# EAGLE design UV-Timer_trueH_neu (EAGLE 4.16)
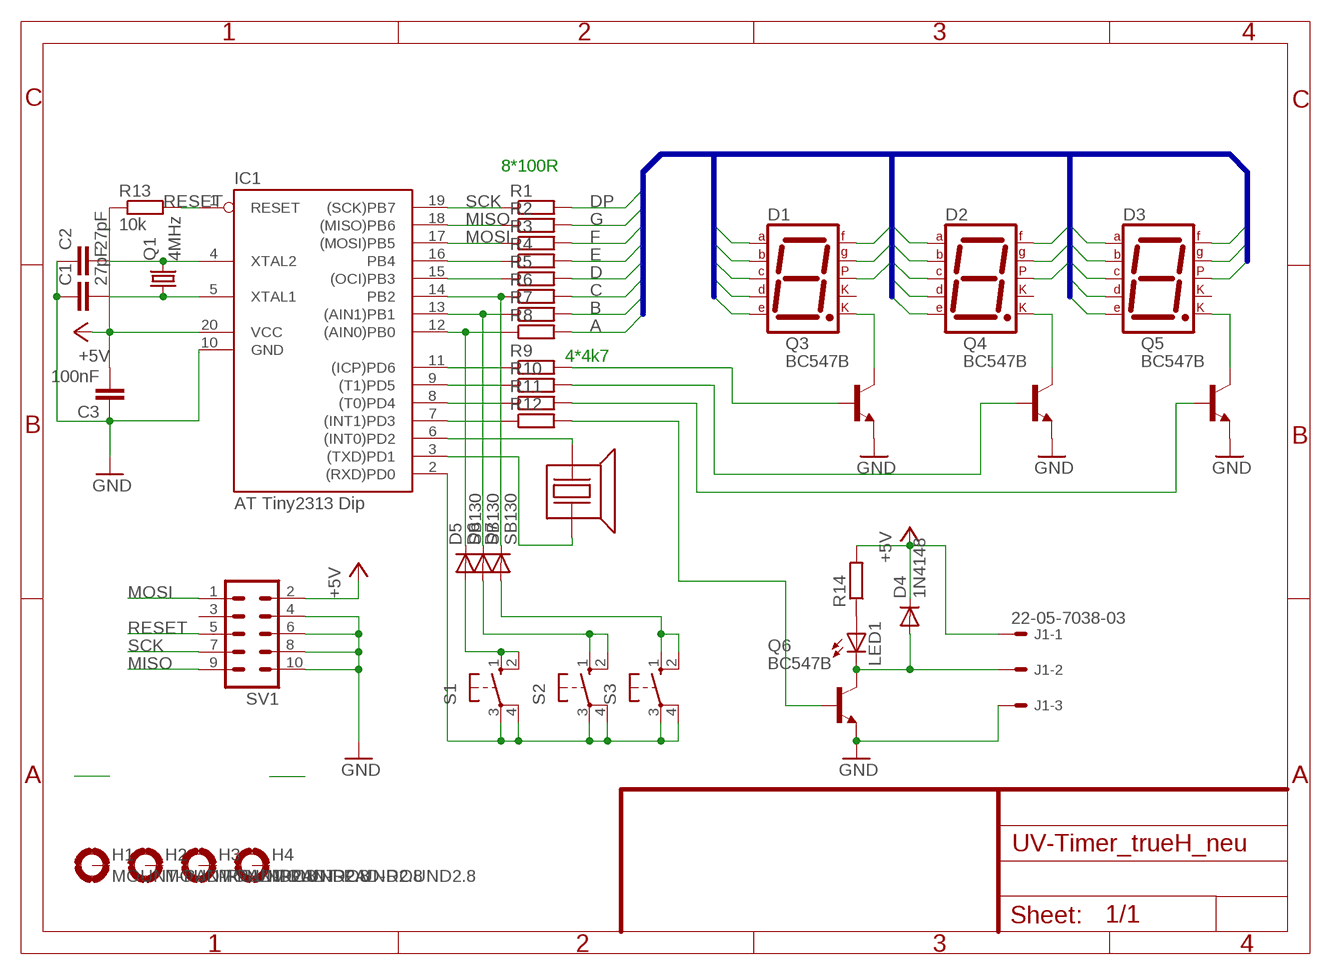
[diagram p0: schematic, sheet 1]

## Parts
BZ1  BUZZ  [BUZZ17.10]
C1  27pF  C-EU025-024X044  [C025-024X044]
C2  27pF  C-EU025-024X044  [C025-024X044]
C3  100nF  C-EU050-024X044  [C050-024X044]
D1  7SEG-CK  [7SEG-13]
D2  7SEG-CK  [7SEG-13]
D3  7SEG-CK  [7SEG-13]
D4  1N4148  4148SMDTRUEHOLE  [DO35-10]
D5  SB130  4148SMDTRUEHOLE  [DO35-10]
D6  SB130  4148SMDTRUEHOLE  [DO35-10]
D7  SB130  4148SMDTRUEHOLE  [DO35-10]
H1  MOUNT-PAD-ROUND2.8  [2,8-PAD]
H2  MOUNT-PAD-ROUND2.8  [2,8-PAD]
H3  MOUNT-PAD-ROUND2.8  [2,8-PAD]
H4  MOUNT-PAD-ROUND2.8  [2,8-PAD]
IC1  AT Tiny2313 Dip  AT90S2313P  [DIL20]
J1  22-05-7038-03  [7395-03]
LED1  LED3MM  [LED3MM]
Q1  4MHz  CRYTALHC49U-V  [HC49U-V]
Q3  BC547B  [TO92]
Q4  BC547B  [TO92]
Q5  BC547B  [TO92]
Q6  BC547B  [TO92]
R1  R-EU_0204/7  [0204/7]
R2  R-EU_0204/7  [0204/7]
R3  R-EU_0204/7  [0204/7]
R4  R-EU_0204/7  [0204/7]
R5  R-EU_0204/7  [0204/7]
R6  R-EU_0204/7  [0204/7]
R7  R-EU_0204/7  [0204/7]
R8  R-EU_0204/7  [0204/7]
R9  R-EU_0204/7  [0204/7]
R10  R-EU_0204/7  [0204/7]
R11  R-EU_0204/7  [0204/7]
R12  R-EU_0204/7  [0204/7]
R13  10k  R-EU_0204/7  [0204/7]
R14  R-EU_0204/7  [0204/7]
S1  10-XX  [B3F-10XX]
S2  10-XX  [B3F-10XX]
S3  10-XX  [B3F-10XX]
SV1  ML10  [ML10]

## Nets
A: D1.7(A) D2.7(A) D3.7(A) R8.2
B: D1.6(B) D2.6(B) D3.6(B) R7.2
C: D1.4(C) D2.4(C) D3.4(C) R6.2
D: D1.2(D) D2.2(D) D3.2(D) R5.2
DP: D1.5(DP) D2.5(DP) D3.5(DP) R1.2
E: D1.1(E) D2.1(E) D3.1(E) R4.2
F: D1.9(F) D2.9(F) D3.9(F) R3.2
G: D1.10(G) D2.10(G) D3.10(G) R2.2
GND: C1.1 C2.1 C3.1 IC1.10(GND) J1.3 Q3.1(E) Q4.1(E) Q5.1(E) Q6.1(E) SV1.4 SV1.6 SV1.8 SV1.10
MISO: IC1.18((MISO)PB6) R2.1 SV1.9
MOSI: IC1.17((MOSI)PB5) R3.1 SV1.1
N$1: IC1.2((RXD)PD0) S1.3(P) S1.4(P1) S2.3(P) S2.4(P1) S3.3(P) S3.4(P1)
N$3: C1.2 IC1.5(XTAL1) Q1.1
N$4: C2.2 IC1.4(XTAL2) Q1.2
N$6: IC1.16(PB4) R4.1
N$7: IC1.15((OCI)PB3) R5.1
N$8: D7.C IC1.14(PB2) R6.1
N$9: D6.C IC1.13((AIN1)PB1) R7.1
N$10: D5.C IC1.12((AIN0)PB0) R8.1
N$11: IC1.11((ICP)PD6) R9.1
N$12: IC1.9((T1)PD5) R10.1
N$13: IC1.8((T0)PD4) R11.1
N$14: IC1.7((INT1)PD3) R12.1
N$15: Q3.2(B) R9.2
N$16: Q4.2(B) R10.2
N$17: Q5.2(B) R11.2
N$18: D1.8(CK2) Q3.3(C)
N$19: D2.8(CK2) Q4.3(C)
N$20: D3.8(CK2) Q5.3(C)
N$21: BZ1.P$2 IC1.6((INT0)PD2)
N$22: Q6.2(B) R12.2
N$23: D5.A S1.1(S) S1.2(S1)
N$24: D6.A S2.1(S) S2.2(S1)
N$25: D7.A S3.1(S) S3.2(S1)
N$26: D4.A J1.2 LED1.K(C) Q6.3(C)
N$27: LED1.A R14.1
N$28: BZ1.P$1 IC1.3((TXD)PD1)
RESET: IC1.1(RESET) R13.2 SV1.5
SCK: IC1.19((SCK)PB7) R1.1 SV1.7
VCC: C3.2 D4.C IC1.20(VCC) J1.1 R13.1 R14.2 SV1.2 ; supply symbol labelled +5V
Unconnected: D1.3(CK1) D2.3(CK1) D3.3(CK1) H1.B2,8(MOUNT) H2.B2,8(MOUNT) H3.B2,8(MOUNT) H4.B2,8(MOUNT) SV1.3

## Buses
BUS:A,B,C,D,E,F,G,DP,K1,K2,K3

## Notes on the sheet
- 8*100R
- 4*4k7

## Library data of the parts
BZ1 = 0_jmw:BUZZ
C1-C3 = rcl:C-EU: CAPACITOR, European symbol
D1-D3 = andereBauteile:7SEG-CK: 7-segment DISPLAY single cathode, 13 mm
D4-D7 = 0_jmw:4148SMD
H1-H4 = holes:MOUNT-PAD-ROUND: MOUNTING PAD, round
IC1 = atmel:AT90S2313: MICROCONTROLLER 2 Kbytes FLASH 128 bytes SRAM 128 bytes EEPROM UART
J1 = EP_molex_6410_7395:22-?-03: CONNECTOR wire to board 2.54 mm (.1 inch) pitch header
LED1 = led:LED: LED
Q1 = crystal:CRYTAL: CRYSTAL
Q3-Q6 = transistor-npn:BC547*: NPN Transistor
R1-R14 = rcl:R-EU_: RESISTOR, European symbol
S1-S3 = switch-omron:10-XX: OMRON SWITCH
SV1 = con-harting-ml:ML10: HARTING

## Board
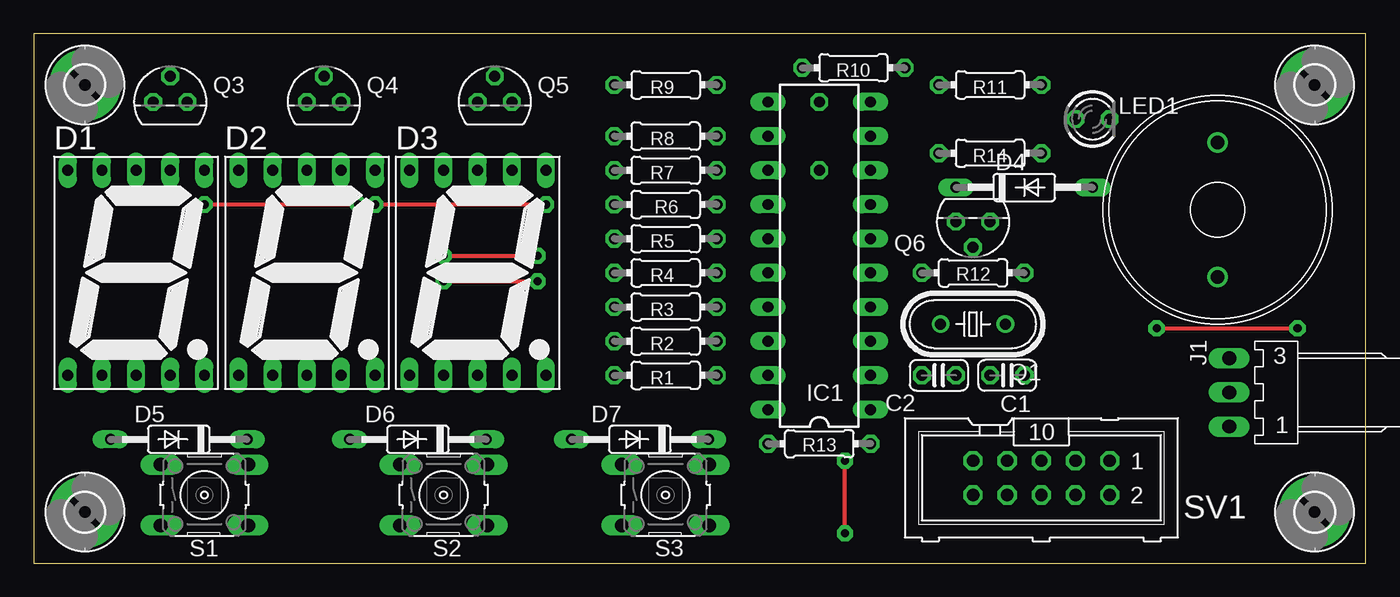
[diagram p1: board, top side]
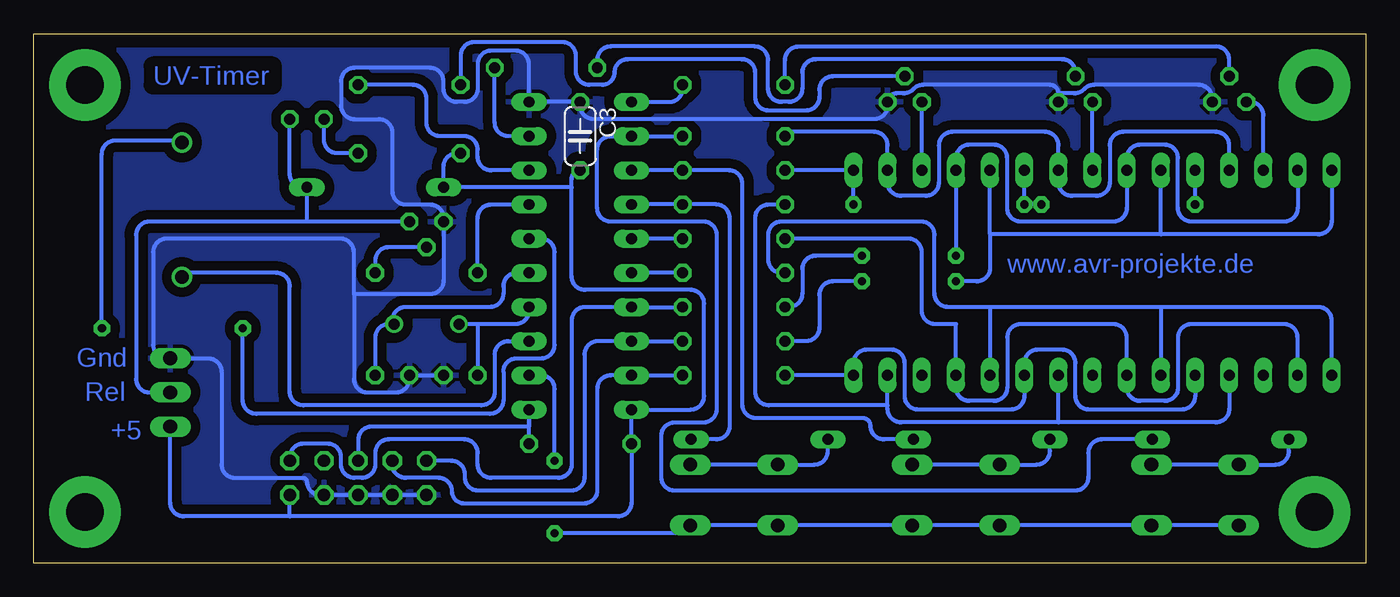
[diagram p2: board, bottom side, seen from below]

Size 99.06 x 39.37 mm. Coordinates in mm from the lower left corner, seen from the top.
Outline: 0,0 99.06,0 99.06,39.37 0,39.37 0,0
Copper layers (1*16): Top 0.035mm / dielectric 1.5mm / Bottom 0.035mm
Design rules "default": minimum track width 10mil, minimum drill 0.4mm, track to track 28mil, track to pad 28mil, pad to pad 28mil, via to via 28mil, smd to smd 10mil, copper to edge 40mil, drill to drill 8mil, minimum pad ring 10mil, minimum via ring 0.3mm, stop-mask expansion 4mil, vias tented up to drill 0mil, thermal gap 10mil

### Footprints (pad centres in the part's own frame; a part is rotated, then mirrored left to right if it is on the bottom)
BUZZ17.10 = drill 1.016 round: P$1 3.5,8.5; P$2 13.5,8.5
C025-024X044 = drill 0.813 octagon: 1 -1.27,0; 2 1.27,0
C050-024X044 = drill 0.813 octagon: 1 -2.54,0; 2 2.54,0
7SEG-13 = drill 0.813 long: 1 -5.08,-7.62; 2 -2.54,-7.62; 3 0,-7.62; 4 2.54,-7.62; 5 5.08,-7.62; 6 5.08,7.62; 7 2.54,7.62; 8 0,7.62; 9 -2.54,7.62; 10 -5.08,7.62
DO35-10 = drill 0.813 long: A 5.08,0; C -5.08,0
2,8-PAD = drill 2.8 pad 5.334 round: B2,8 0,0
DIL20 = drill 0.813 long: 1 -11.43,-3.81; 2 -8.89,-3.81; 3 -6.35,-3.81; 4 -3.81,-3.81; 5 -1.27,-3.81; 6 1.27,-3.81; 7 3.81,-3.81; 8 6.35,-3.81; 9 8.89,-3.81; 10 11.43,-3.81; 11 11.43,3.81; 12 8.89,3.81; 13 6.35,3.81; 14 3.81,3.81; 15 1.27,3.81; 16 -1.27,3.81; 17 -3.81,3.81; 18 -6.35,3.81; 19 -8.89,3.81; 20 -11.43,3.81
7395-03 = drill 1.016 long: 1 2.54,0; 2 0,0; 3 -2.54,0
LED3MM = drill 0.813 octagon: A -1.27,0; K 1.27,0
HC49U-V = drill 0.813 round: 1 -2.413,0; 2 2.413,0
TO92 = drill 0.813 octagon: 1 1.27,0; 2 0,1.905; 3 -1.27,0
0204/7 = drill 0.813 octagon: 1 -3.81,0; 2 3.81,0
B3F-10XX = drill 1.016 long: 1 -3.251,2.261; 2 3.251,2.261; 3 -3.251,-2.261; 4 3.251,-2.261
ML10 = drill 0.914 octagon: 1 -5.08,-1.27; 2 -5.08,1.27; 3 -2.54,-1.27; 4 -2.54,1.27; 5 0,-1.27; 6 0,1.27; 7 2.54,-1.27; 8 2.54,1.27; 9 5.08,-1.27; 10 5.08,1.27

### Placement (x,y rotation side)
BZ1  96.52,17.78 90 top
C1  72.39,13.97 0 top
C2  67.31,13.97 180 top
C3  58.42,31.75 270 bottom
D1  7.62,21.59 0 top
D2  20.32,21.59 0 top
D3  33.02,21.59 0 top
D4  73.66,27.94 0 top
D5  10.79,9.21 180 top
D6  28.57,9.21 180 top
D7  45.09,9.21 180 top
H1  95.25,35.56 0 top
H2  3.81,3.81 0 top
H3  3.81,35.56 0 top
H4  95.25,3.81 0 top
IC1  58.42,22.86 90 top
J1  88.9,12.7 270 top
LED1  78.74,33.02 0 top
Q1  69.85,17.78 180 top
Q3  10.16,34.29 0 top
Q4  21.59,34.29 0 top
Q5  34.29,34.29 0 top
Q6  69.85,25.4 180 top
R1  46.99,13.97 180 top
R2  46.99,16.51 180 top
R3  46.99,19.05 180 top
R4  46.99,21.59 180 top
R5  46.99,24.13 180 top
R6  46.99,26.67 180 top
R7  46.99,29.21 180 top
R8  46.99,31.75 180 top
R9  46.99,35.56 180 top
R10  60.96,36.83 180 top
R11  71.12,35.56 180 top
R12  69.85,21.59 0 top
R13  58.42,8.89 0 top
R14  71.12,30.48 180 top
S1  12.7,5.08 0 top
S2  30.48,5.08 0 top
S3  46.99,5.08 0 top
SV1  74.93,6.35 180 top

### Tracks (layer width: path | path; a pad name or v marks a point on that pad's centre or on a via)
A
  Bottom 0.305: D1.7 10.16,31.07 arc-90 11.16,32.07 18.05,32.07 arc-90 19.05,31.07 19.05,28.3 arc90 20.05,27.3 21.86,27.3 arc90 22.86,28.3 D2.7 22.86,31.07 arc-90 23.86,32.07 30.75,32.07 arc-90 31.75,31.07 31.75,28.3 arc90 32.75,27.3 34.56,27.3 arc90 35.56,28.3 D3.7 35.56,31.07 arc-90 36.56,32.07 43.18,32.07 R8.2
B  (via drill 0.6)
  Top 0.305: v12.7,26.67 v24.13,26.67 | v25.4,26.67 v38.1,26.67
  Bottom 0.305: v12.7,26.67 D1.6 | v24.13,26.67 v25.4,26.67 D2.6 | v38.1,26.67 D3.6 R7.2
C
  Bottom 0.305: D1.4 10.16,11.48 arc90 11.16,10.48 22.86,10.48 | 22.86,10.48 34.56,10.48 arc90 35.56,11.48 35.56,11.75 | 22.86,10.48 D2.4 | R6.2 44.4,26.67 arc-90 45.4,25.67 45.4,12.75 arc-90 44.4,11.75 35.56,11.75 | 35.56,11.75 D3.4
D
  Bottom 0.305: D1.2 5.08,16.78 arc-90 6.08,17.78 12.97,17.78 arc-90 13.97,16.78 13.97,13.06 arc90 14.97,12.06 16.78,12.06 arc90 17.78,13.06 D2.2 17.78,16.78 arc-90 18.78,17.78 25.67,17.78 arc-90 26.67,16.78 26.67,13.06 arc90 27.67,12.06 29.48,12.06 arc90 30.48,13.06 D3.2 | D3.2 30.48,13.65 | D3.2 30.48,17.78 32.02,17.78 arc90 33.02,18.78 33.02,23.13 arc-90 34.02,24.13 R5.2
DP
  Bottom 0.305: D1.5 12.7,12.43 arc90 13.7,11.43 20.59,11.43 arc90 21.59,12.43 21.59,14.88 arc-90 22.59,15.88 24.4,15.88 arc-90 25.4,14.88 D2.5 25.4,12.43 arc90 26.4,11.43 33.29,11.43 arc90 34.29,12.43 34.29,14.88 arc-90 35.29,15.88 37.1,15.88 arc-90 38.1,14.88 D3.5 R1.2
E
  Bottom 0.305: D1.1 2.54,18.05 arc-90 3.54,19.05 15.24,19.05 | 15.24,19.05 27.94,19.05 | 27.94,19.05 D3.1 | 15.24,19.05 D2.1 | R4.2 43.45,21.59 arc90 44.45,22.59 44.45,24.4 arc90 43.45,25.4 33.07,25.4 arc90 32.07,24.4 32.07,20.05 arc-90 31.07,19.05 27.94,19.05
F  (via drill 0.6)
  Top 0.305: v30.48,22.86 v37.47,22.86
  Bottom 0.305: D1.9 5.08,26.4 arc90 6.08,25.4 12.97,25.4 arc90 13.97,26.4 13.97,30.11 arc-90 14.97,31.11 16.78,31.11 arc-90 17.78,30.11 D2.9 17.78,26.4 arc90 18.78,25.4 25.67,25.4 arc90 26.67,26.4 26.67,30.11 arc-90 27.67,31.11 29.48,31.11 arc-90 30.48,30.11 D3.9 | R3.2 42.91,19.05 arc-90 41.91,20.05 41.91,21.86 arc90 40.91,22.86 v37.47,22.86 | D3.9 v30.48,22.86 | D3.9 30.16,29.21
G  (via drill 0.6)
  Top 0.305: v30.48,20.95 v37.47,20.95
  Bottom 0.305: D1.10 2.54,25.45 arc90 3.54,24.45 15.24,24.45 | 15.24,24.45 27.94,24.45 | 27.94,24.45 D3.10 | 15.24,24.45 D2.10 | v37.47,20.95 39.64,20.95 arc-90 40.64,19.95 40.64,17.51 arc90 41.64,16.51 R2.2 | 27.94,24.45 27.94,21.95 arc90 28.94,20.95 v30.48,20.95
GND
  Bottom 0.305: SV1.10 SV1.8 SV1.6 | SV1.4 SV1.6 | C2.1 C1.1 71.12,13.7 arc90 72.12,12.7 74.25,12.7 arc90 75.25,13.7 75.25,20 | 75.25,20 69.58,20 arc-90 68.58,21 Q6.1 68.58,25.67 arc-90 69.58,26.67 71.39,26.67 arc90 72.39,27.67 72.39,32.02 arc-90 73.39,33.02 75.2,33.02 arc90 76.2,34.02 76.2,35.83 arc90 75.2,36.83 69.58,36.83 arc90 68.58,35.83 68.58,35.29 arc-90 67.58,34.29 67.04,34.29 arc-90 66.04,35.29 66.04,37.1 arc90 65.04,38.1 63.23,38.1 arc90 62.23,37.1 IC1.10 C3.1 58.42,34.02 arc-90 57.42,33.02 36.56,33.02 arc-90 35.56,34.02 Q5.1 arc90 34.92,34.92 34.39,34.92 arc-45 33.68,35.22 33.63,35.27 arc45 32.92,35.56 23.5,35.56 arc90 22.86,34.92 | 75.25,20 75.25,23.13 arc-90 76.25,24.13 89.17,24.13 arc-90 90.17,23.13 90.17,16.24 arc-90 89.17,15.24 J1.3 86.09,15.24 arc90 85.09,14.24 85.09,7.35 arc-90 84.09,6.35 79.01,6.35 arc90 78.74,6.08 arc-90 77.74,5.08 SV1.4 | SV1.4 SV1.6 | 22.86,34.92 Q4.1 | Q3.1 11.43,34.56 arc-90 12.43,35.56 20.22,35.56 arc-45 20.93,35.27 20.98,35.22 arc45 21.69,34.92 22.86,34.92
  pour Bottom: 0,39.37 99.06,39.37 99.06,0 0,0
MISO
  Bottom 0.305: R2.1 IC1.18 57.1,16.51 arc-90 58.1,15.51 58.1,6.4 arc90 59.1,5.4 65.99,5.4 arc90 66.99,6.4 66.99,6.62 arc-90 67.99,7.62 SV1.9
MOSI
  Bottom 0.305: R3.1 IC1.17 58.05,19.05 arc-90 59.05,18.05 59.05,7.35 arc90 60.05,6.35 65.04,6.35 arc90 66.04,7.35 66.04,8.21 arc-90 67.04,9.21 72.66,9.21 arc-90 73.66,8.21 73.66,7.35 arc90 74.66,6.35 75.2,6.35 arc90 76.2,7.35 76.2,7.89 arc-90 77.2,8.89 79.01,8.89 arc-90 80.01,7.89 SV1.1
N$1  (via drill 0.6)
  Top 0.305: v60.33,2.22 v60.33,7.62
  Bottom 0.305: S1.3 S1.4 | S1.4 16.51,2.82 16.51,2.54 16.19,2.54 16.19,2.82 | 16.19,2.82 16.19,2.86 | S1.4 16.19,2.82 | S1.4 S2.3 | S2.3 27.3,2.82 27.3,2.54 | 33.66,2.82 S2.4 S3.3 | S2.3 33.66,2.82 | 33.66,2.82 33.66,2.86 | S3.3 43.81,2.82 43.81,2.54 | S3.3 50.16,2.82 | v60.33,7.62 60.33,12.97 arc-90 61.33,13.97 IC1.2 | 50.16,2.82 50.16,2.86 | 50.16,2.82 S3.4 | 50.16,2.82 arc90 50.76,2.22 v60.33,2.22
N$3
  Bottom 0.305: 72.39,17.78 72.66,17.78 arc-90 73.66,16.78 C1.2 | IC1.5 63.13,21.59 arc-90 64.14,20.59 64.14,20.05 arc90 65.14,19.05 71.39,19.05 arc-90 72.39,18.05 72.39,17.78 | 72.39,17.78 Q1.1
N$4
  Bottom 0.305: 66.04,17.78 Q1.2 | 66.04,17.78 C2.2 | IC1.4 62.23,18.78 arc90 63.23,17.78 66.04,17.78
N$6
  Bottom 0.305: R4.1 IC1.16
N$7
  Bottom 0.305: R5.1 IC1.15
N$8
  Bottom 0.305: IC1.14 R6.1 48.31,26.67 arc90 47.31,25.67 47.31,10.21 arc90 48.31,9.21 D7.C
N$9
  Bottom 0.305: R7.1 IC1.13 | D6.C 35.83,9.21 arc90 36.83,10.21 arc-90 37.42,10.79 45.35,10.79 arc90 46.35,11.79 46.35,28.21 arc-90 47.35,29.21 R7.1 | R7.1 50.8,28.89
N$10
  Bottom 0.305: R8.1 IC1.12 54.93,31.75 | D5.C 19.64,9.21 arc-90 20.64,8.21 20.64,6.4 arc90 21.64,5.4 51.39,5.4 arc90 52.39,6.4 52.39,9.48 arc90 51.39,10.48 49.26,10.48 arc-90 48.26,11.48 48.26,24.4 arc-90 49.26,25.4 56.15,25.4 arc90 57.15,26.4 57.15,30.75 arc90 56.15,31.75 54.93,31.75 | 54.93,31.75 54.93,32.07
N$11
  Bottom 0.305: IC1.11 51.8,34.29 arc-90 50.8,35.29 R9.1
N$12
  Bottom 0.305: IC1.9 63.77,31.75 arc90 64.77,32.75 R10.1
N$13
  Bottom 0.305: IC1.8 65.04,29.21 arc90 66.04,30.21 66.04,30.75 arc-90 67.04,31.75 68.85,31.75 arc90 69.85,32.75 69.85,34.56 arc-90 70.85,35.56 R11.1
N$14
  Bottom 0.305: R12.1 66.04,25.67 arc90 65.04,26.67 IC1.7
N$15
  Bottom 0.305: Q3.2 10.16,37.42 arc-90 11.16,38.42 42.18,38.42 arc-90 43.18,37.42 R9.2
N$16
  Bottom 0.305: Q4.2 21.59,36.47 arc-90 22.59,37.47 40.91,37.47 arc-90 41.91,36.47 41.91,35.29 arc90 42.91,34.29 43.45,34.29 arc90 44.45,35.29 44.45,37.42 arc-90 45.45,38.42 56.15,38.42 arc-90 57.15,37.42 R10.2
N$17
  Bottom 0.305: Q5.2 39.64,36.2 arc-90 40.64,35.2 40.64,34.66 arc90 41.64,33.66 44.4,33.66 arc90 45.4,34.66 45.4,36.47 arc-90 46.4,37.47 54.88,37.47 arc-90 55.88,36.47 arc90 56.78,35.56 57.74,35.56 arc90 58.74,36.56 58.74,37.73 arc-90 59.74,38.73 66.31,38.73 arc-90 67.31,37.73 R11.2
N$18
  Bottom 0.305: D1.8 7.62,33.29 arc-90 8.62,34.29 Q3.3
N$19
  Bottom 0.305: D2.8 Q4.3
N$20
  Bottom 0.305: D3.8 Q5.3
N$21  (via drill 0.6)
  Top 0.305: v83.5,17.46 v93.98,17.46
  Bottom 0.305: IC1.6 61.33,24.13 arc90 60.33,23.13 60.33,16.24 arc90 61.33,15.24 63.13,15.24 arc-90 64.14,14.24 64.14,12.11 arc90 65.14,11.11 82.5,11.11 arc90 83.5,12.11 v83.5,17.46 | BZ1.P$2 88.02,31.43 92.98,31.43 arc-90 93.98,30.43 v93.98,17.46
N$22
  Bottom 0.305: Q6.2 72.66,23.5 arc-90 73.66,22.5 R12.2
N$23
  Bottom 0.305: D5.A 5.71,8.34 arc90 6.71,7.34 S1.1 15.88,7.34 | 15.88,7.34 S1.2 | 15.88,7.34 15.88,7.3
N$24
  Bottom 0.305: D6.A 23.5,8.34 arc90 24.5,7.34 S2.1 33.66,7.34 | 33.66,7.34 S2.2 | 33.66,7.34 33.66,7.62
N$25
  Bottom 0.305: D7.A 40.01,8.34 arc90 41.01,7.34 S3.1 50.48,7.34 | 50.48,7.34 S3.2 | 50.48,7.34 50.48,7.3
N$26
  Bottom 0.305: Q6.3 78.74,25.4 | 78.74,25.4 D4.A 79.01,27.94 arc90 80.01,28.94 LED1.K | J1.2 90.44,12.7 arc90 91.44,13.7 91.44,24.4 arc90 90.44,25.4 78.74,25.4
N$27
  Bottom 0.305: R14.1 76.47,30.48 arc90 77.47,31.48 LED1.A
N$28
  Bottom 0.305: IC1.3 63.77,16.51 arc-90 64.77,15.51 64.77,12.75 arc90 65.77,11.75 79.01,11.75 arc90 80.01,12.75 80.01,20.59 arc-90 81.01,21.59 88.02,21.59 BZ1.P$1
RESET
  Bottom 0.305: R13.2 IC1.1 62.23,10.16 73.93,10.16 arc-90 74.93,9.16 SV1.5
SCK
  Bottom 0.305: R1.1 IC1.19 56.15,13.97 arc-90 57.15,12.97 57.15,5.45 arc90 58.15,4.45 67.04,4.45 arc90 67.94,5.35 arc-90 68.94,6.35 71.39,6.35 arc90 72.39,7.35 SV1.7
VCC
  Bottom 0.305: 80.01,3.49 55.61,3.49 arc-90 54.61,4.49 R13.1 IC1.20 50.21,11.43 arc-90 49.21,12.43 49.21,19.32 arc-90 50.21,20.32 58.05,20.32 arc90 59.05,21.32 59.05,27.94 | 80.01,3.49 SV1.2 | 80.01,3.49 87.9,3.49 arc90 88.9,4.49 J1.1 | 59.05,27.94 D4.C 68.58,29.48 arc90 67.58,30.48 R14.2 | 59.05,27.94 59.05,28.57 arc90 C3.2

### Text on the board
Bottom: UV-Timer | www.avr-projekte.de | Gnd | Rel | +5
Bohrschablone: led | buzz | taster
